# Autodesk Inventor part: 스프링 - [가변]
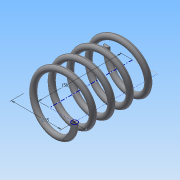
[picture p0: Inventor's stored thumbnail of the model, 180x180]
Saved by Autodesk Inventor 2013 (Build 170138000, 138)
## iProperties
Created: 2015-03
Part Number: 스프링 - [가변]
Material: 강철, 탄소
Document SubType Name: Modeling
Designer: Administrator
Density: 7.87 g/cm^3
Mass: 47.9935 g
Surface Area: 62.0176 cm^2
Volume: 6.09829 cm^3
Author: Administrator
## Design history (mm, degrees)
sketch "스케치1"
  geometry: L1 (0, 0)-(17.5, 0); L2 (17.5, 0)-(17.5, 43.5); L3 (17.5, 43.5)-(0, 43.5); L4 (0, 43.5)-(0, 0); C1 r 2 at (17.5, 0)
  constraints: 8 end point, 2 parallel, 1 centre point, 1 coincident, 1 horizontal, 1 perpendicular
  dimensions: "d0" = 4 diameter of C1; "d2" = 35 diameter of L2 L4; "d3" = 43.5 distance of L3.end L1.start (derived)
feature "코일1" sketch "스케치1" pitch "d4" = 10; turns "d6" = 4.5; dims "d5" = 43.5 (= d3), "d7" = 0, angle "d8" = 90 deg, angle "d9" = 90 deg, "d10" = 0, "d11" = 0
node "작업 평면1"
sketch "스케치2"
  geometry: L1 (-19.5, 0)-(-15.5, 0) reference; 1 further point
  constraints: 1 horizontal alignment
extrude "돌출1" cut sketch "스케치2" stored distance "d13" = 10; taper "d14" = 0 deg
sketch "스케치3"
  geometry: L1 (15.5, 0)-(19.5, 0) reference; 1 further point
  constraints: 1 horizontal alignment
extrude "돌출2" cut sketch "스케치3" stored distance "d15" = 10; taper "d16" = 0 deg
node "솔리드1"
node "절단 모서리 투영1"
node "절단 모서리 투영2"
other parameters: "d12" = 43.5 (= d3)
